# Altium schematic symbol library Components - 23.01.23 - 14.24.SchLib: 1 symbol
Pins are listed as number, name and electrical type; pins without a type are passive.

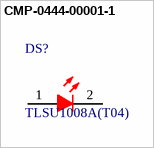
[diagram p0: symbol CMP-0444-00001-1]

## CMP-0444-00001-1
designator DS?, comment TLSU1008A(T04)
LED, Red 0603 (1608) 63mCd; Manufacturer: Toshiba; Forward Current: 25 mA; Power Dissipation: 60 mW; Packing Type: Reel; Reverse Voltage: 4 V
footprint TOSH-0603LED_RED_V (SMT LED, 2-Leads, Body 1.6x0.8mm (0603-Size))
pins: 1 A, 2 K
